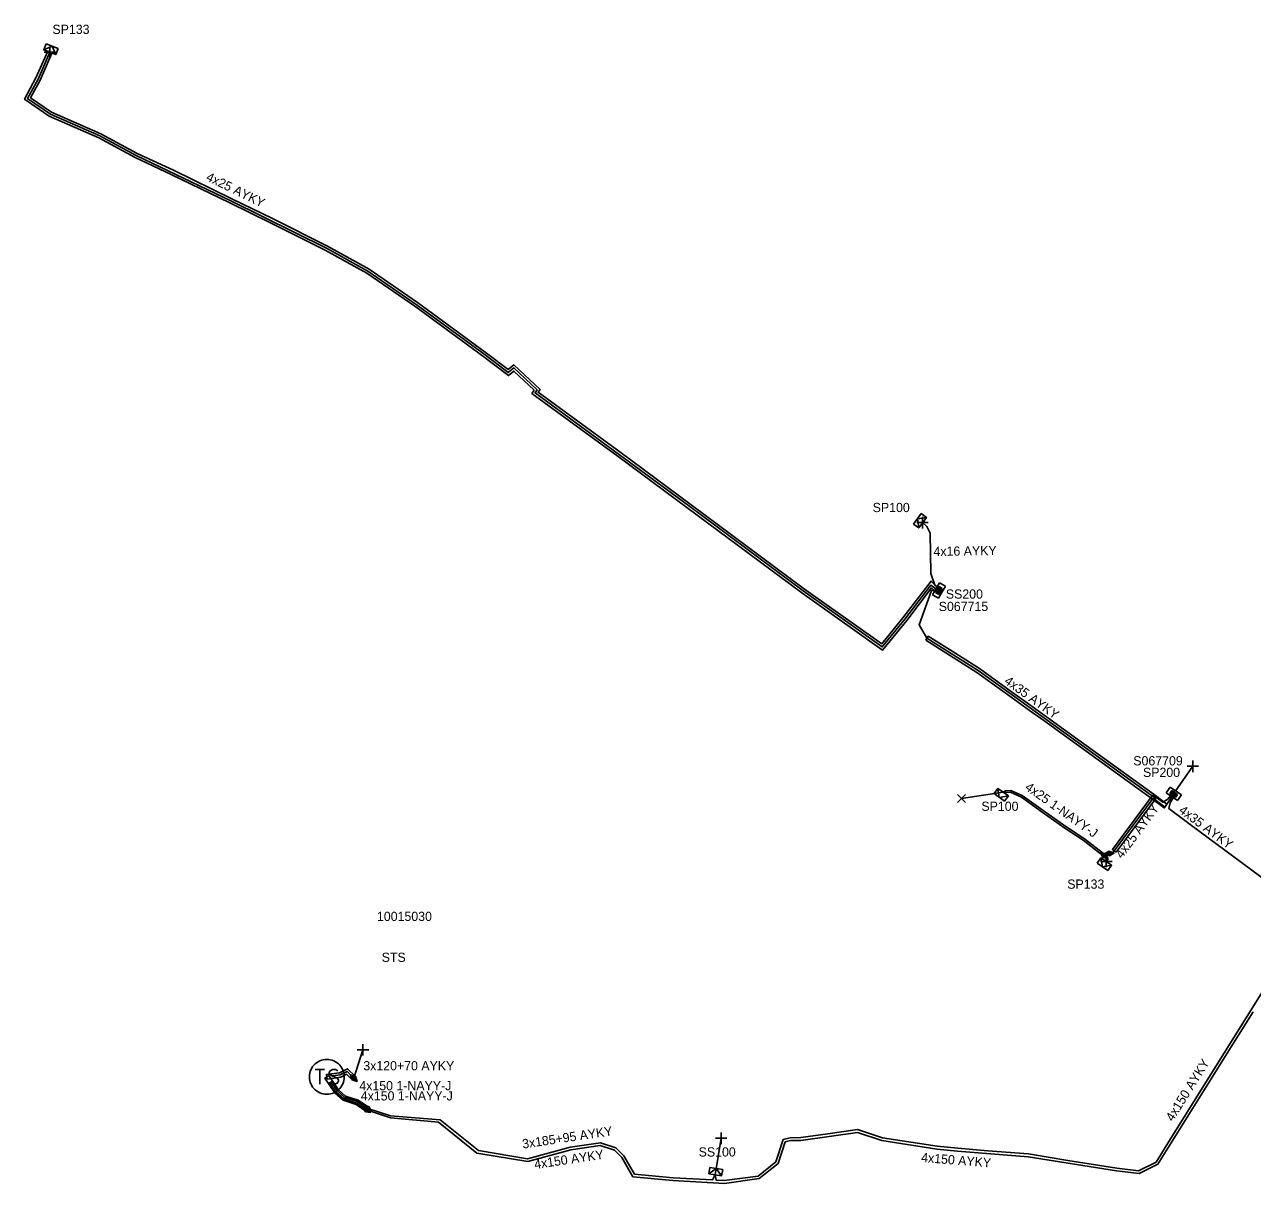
# Model space of a CAD drawing. Extents: x -748492 to -735633, y -1146251 to -1139940.
# Drawn here: x -737058.1 to -736925.2, y -1144906.3 to -1144780.8 of the extents above; entities that cross this region are included whole.
import ezdxf

# ---------------------------------------------------------------- set-up
doc = ezdxf.new("R2010")
doc.units = 0
for name, color, linetype in [('Vrstva 1', 7, 'Continuous'), ('Vrstva 19', 7, 'Continuous'), ('Vrstva 20', 7, 'Continuous'), ('Vrstva 25', 7, 'Continuous'), ('Vrstva 26', 7, 'Continuous'), ('Vrstva 27', 7, 'Continuous'), ('Vrstva 28', 7, 'Continuous'), ('Vrstva 29', 7, 'Continuous'), ('Vrstva 30', 7, 'Continuous'), ('Vrstva 31', 7, 'Continuous'), ('Vrstva 33', 7, 'Continuous'), ('Vrstva 34', 7, 'Continuous'), ('Vrstva 4', 7, 'Continuous'), ('Vrstva 5', 7, 'Continuous'), ('Vrstva 52', 7, 'Continuous'), ('Vrstva 54', 7, 'Continuous'), ('Vrstva 59', 7, 'Continuous'), ('Vrstva 6', 7, 'Continuous'), ('Vrstva 8', 7, 'Continuous'), ('Vrstva 9', 7, 'Continuous')]:
    doc.layers.add(name, color=color, linetype=linetype)

# ---------------------------------------------------------------- blocks, each defined once
blk = doc.blocks.new('NN870')
at = {"layer": 'Vrstva 4'}
for points in [[(0, -0.25), (0.5, 0), (0, 0.25), (-0.5, 0), (0, -0.25)], [(0.37, 0), (0, 0.19), (-0.36, 0), (0, -0.19), (0.37, 0)], [(0.24, 0), (0, 0.12), (-0.25, 0), (0, -0.12), (0.24, 0)], [(0.12, 0), (0, 0.06), (-0.13, 0), (0, -0.06), (0.12, 0)]]:
    blk.add_lwpolyline(points, dxfattribs=at)
blk = doc.blocks.new('NN800')
at = {"layer": 'Vrstva 1'}
for points in [[(-0.44, 0.44), (0.44, -0.44)], [(-0.44, -0.44), (0.44, 0.44)]]:
    blk.add_lwpolyline(points, dxfattribs=at)
blk = doc.blocks.new('NN620')
at = {"layer": 'Vrstva 8'}
for points in [[(0.75, 0), (-0.75, 0)], [(-0.75, 0), (-0.75, -0.75)], [(0.75, -0.75), (0.75, 0)], [(-0.75, -0.75), (0.75, -0.75)], [(0.37, -0.18), (-0.38, -0.18)], [(-0.38, -0.18), (-0.38, -0.56)], [(-0.38, -0.56), (0.37, -0.56)], [(0.32, -0.23), (-0.33, -0.23)], [(-0.33, -0.23), (-0.33, -0.51)], [(-0.33, -0.51), (0.32, -0.51)], [(0.27, -0.27), (-0.28, -0.27)], [(-0.28, -0.27), (-0.28, -0.46)], [(-0.28, -0.46), (0.27, -0.46)], [(0.23, -0.32), (-0.23, -0.32)], [(-0.23, -0.32), (-0.23, -0.42)], [(-0.23, -0.42), (0.23, -0.42)], [(-0.19, -0.37), (0.19, -0.37)], [(0.23, -0.42), (0.23, -0.32)], [(0.27, -0.46), (0.27, -0.27)], [(0.32, -0.51), (0.32, -0.23)], [(0.37, -0.56), (0.37, -0.18)]]:
    blk.add_lwpolyline(points, dxfattribs=at)
blk = doc.blocks.new('NN630')
at = {"layer": 'Vrstva 9'}
for points in [[(0, -0.7), (-0.7, 0)], [(-0.7, -0.7), (-0.7, 0), (0.7, 0), (0.7, -0.7)], [(-0.7, -0.7), (0.7, -0.7)], [(0, -0.7), (0.7, 0)]]:
    blk.add_lwpolyline(points, dxfattribs=at)
blk = doc.blocks.new('NN610')
at = {"layer": 'Vrstva 6'}
for points in [[(1.88, 0), (1.87, 0.2), (1.84, 0.39), (1.79, 0.58), (1.72, 0.77), (1.63, 0.94), (1.52, 1.11), (1.4, 1.26), (1.26, 1.4), (1.1, 1.53), (0.94, 1.63), (0.76, 1.72), (0.58, 1.8), (0.19, 1.88), (0.19, 1.88), (-0.01, 1.89), (-0.21, 1.88), (-0.4, 1.85), (-0.59, 1.8), (-0.78, 1.72), (-0.95, 1.63), (-1.12, 1.53), (-1.27, 1.4), (-1.41, 1.26), (-1.54, 1.11), (-1.64, 0.94), (-1.73, 0.77), (-1.8, 0.58), (-1.86, 0.39), (-1.89, 0.2), (-1.9, 0), (-1.89, -0.2), (-1.86, -0.39), (-1.8, -0.58), (-1.73, -0.77), (-1.64, -0.95), (-1.54, -1.11), (-1.41, -1.27), (-1.27, -1.41), (-1.12, -1.53), (-0.95, -1.64), (-0.78, -1.73), (-0.59, -1.8), (-0.4, -1.85), (-0.21, -1.88), (-0.01, -1.89), (0.19, -1.88), (0.39, -1.85), (0.58, -1.8), (0.76, -1.73), (0.94, -1.64), (1.1, -1.53), (1.26, -1.41), (1.4, -1.27), (1.52, -1.11), (1.63, -0.95), (1.72, -0.77), (1.79, -0.58), (1.84, -0.39), (1.87, -0.2), (1.88, 0)], [(-1.27, 0.78), (-0.26, 0.78)], [(-0.76, 0.78), (-0.76, -0.79)], [(1.19, 0.66), (0.94, 0.78), (0.62, 0.78), (0.37, 0.66), (0.24, 0.47), (0.24, 0.4), (0.37, 0.22), (1.12, -0.16), (1.25, -0.32), (1.25, -0.48), (1.12, -0.67), (0.87, -0.79), (0.62, -0.79), (0.49, -0.73), (0.24, -0.6)]]:
    blk.add_lwpolyline(points, dxfattribs=at)

msp = doc.modelspace()

# ---------------------------------------------------------------- linework, layer by layer
at = {"layer": 'Vrstva 20'}
for points in [[(-736959.58, -1144842.09), (-736959.88, -1144841.81), (-736962.58, -1144845.36), (-736965.18, -1144848.54), (-736973.94, -1144842.35), (-736986.36, -1144833.11), (-736993.8, -1144827.6), (-737003.15, -1144820.76), (-737002.92, -1144820.42), (-737005.12, -1144818.34), (-737005.69, -1144818.83), (-737008.49, -1144816.69), (-737015.82, -1144811.32), (-737021.03, -1144807.75), (-737025.51, -1144805.27), (-737031.45, -1144802.28), (-737035.85, -1144800.14), (-737042.18, -1144797.06), (-737046.11, -1144795.22), (-737050.02, -1144793.09), (-737055.39, -1144790.75), (-737058.07, -1144788.91), (-737056.83, -1144786.62), (-737055.56, -1144783.73), (-737055.1, -1144783.93), (-737056.38, -1144786.84), (-737057.41, -1144788.75), (-737055.15, -1144790.31), (-737049.8, -1144792.65), (-737045.89, -1144794.78), (-737041.96, -1144796.6), (-737035.63, -1144799.69), (-737031.23, -1144801.84), (-737025.27, -1144804.83), (-737020.77, -1144807.33), (-737015.53, -1144810.92), (-737008.19, -1144816.29), (-737005.71, -1144818.19), (-737005.1, -1144817.68), (-737002.26, -1144820.34), (-737002.47, -1144820.64), (-736993.5, -1144827.2), (-736986.06, -1144832.71), (-736973.64, -1144841.95), (-736965.28, -1144847.86), (-736962.98, -1144845.05), (-736959.94, -1144841.07), (-736959.24, -1144841.73)], [(-736960.52, -1144847.47), (-736960.26, -1144847.05), (-736957.67, -1144848.67), (-736954.7, -1144850.54), (-736951.36, -1144852.94), (-736949, -1144854.66), (-736947.45, -1144855.76), (-736945.62, -1144857.1), (-736935.66, -1144864.27), (-736934.4, -1144865.24), (-736934.7, -1144865.64), (-736935.96, -1144864.67), (-736945.91, -1144857.51), (-736947.74, -1144856.17), (-736949.29, -1144855.07), (-736951.65, -1144853.34), (-736954.98, -1144850.96), (-736957.94, -1144849.09)], [(-736939.91, -1144870.42), (-736940.31, -1144870.12), (-736936.01, -1144864.32), (-736935.61, -1144864.62)], [(-737025.13, -1144894.6), (-737024.11, -1144896.13), (-737023.31, -1144896.83), (-737021.96, -1144897.28), (-737020.84, -1144898.04), (-737021.12, -1144898.46), (-737022.18, -1144897.74), (-737023.57, -1144897.27), (-737024.49, -1144896.47), (-737025.55, -1144894.88)], [(-737025.38, -1144894.49), (-737023.98, -1144894.29), (-737023.1, -1144893.86), (-737022.24, -1144894.71), (-737022.6, -1144895.07), (-737023.2, -1144894.46), (-737023.82, -1144894.77), (-737025.3, -1144894.99)]]:
    msp.add_lwpolyline(points, close=True, dxfattribs=at)
at = {"layer": 'Vrstva 5'}
for points in [[(-736959.51, -1144842.09), (-736959.91, -1144842.09), (-736961.24, -1144845.8), (-736960.39, -1144847.26), (-736954.84, -1144850.75), (-736951.52, -1144853.15), (-736947.36, -1144856.14), (-736936.11, -1144864.25), (-736935.72, -1144864.35), (-736934.86, -1144865.01), (-736934.32, -1144864.69), (-736934.01, -1144864.31)], [(-736940.65, -1144870.56), (-736941.26, -1144870.58), (-736943.34, -1144868.98), (-736945.34, -1144867.65), (-736947.79, -1144865.92), (-736950.06, -1144864.3), (-736951.3, -1144863.74), (-736951.87, -1144863.8), (-736952.14, -1144863.93), (-736951.73, -1144863.98), (-736951.34, -1144863.94), (-736950.16, -1144864.48), (-736947.91, -1144866.08), (-736945.46, -1144867.81), (-736943.46, -1144869.14), (-736941.48, -1144870.66), (-736941.19, -1144870.79)], [(-736933.88, -1144864.42), (-736934.64, -1144865.56), (-736935.9, -1144864.59), (-736940.21, -1144870.42), (-736940.65, -1144870.56)], [(-736933.7, -1144864.52), (-736934.04, -1144865.07), (-736934.19, -1144865.71), (-736931.73, -1144867.53), (-736921.6, -1144875.04), (-736919.22, -1144874.32), (-736920.26, -1144873.68)], [(-736983.3, -1144905.34), (-736983.2, -1144905.93), (-736982.33, -1144905.98), (-736978.66, -1144905.48), (-736976.75, -1144903.94), (-736975.96, -1144901.54), (-736975.18, -1144901.33), (-736974.04, -1144901.32), (-736971.1, -1144900.91), (-736967.89, -1144900.45), (-736965.19, -1144901.34), (-736959.29, -1144902.26), (-736957.04, -1144902.48), (-736953.8, -1144902.74), (-736949.38, -1144903.09), (-736945.14, -1144903.78), (-736939.83, -1144904.63), (-736937.49, -1144904.9), (-736935.59, -1144903.96), (-736934.03, -1144901.45), (-736931.98, -1144898.17), (-736923.56, -1144884.72)], [(-737021.04, -1144898.33), (-737018.47, -1144899.18), (-737013.27, -1144899.65), (-737009.1, -1144902.99), (-737003.6, -1144903.9), (-736998.95, -1144902.66), (-736995.75, -1144902.18), (-736994.21, -1144902.67), (-736993.43, -1144903.48), (-736992.21, -1144905.55), (-736987.88, -1144905.98), (-736982.31, -1144906.28), (-736978.54, -1144905.76), (-736976.49, -1144904.12), (-736975.72, -1144901.78), (-736975.14, -1144901.63), (-736974.02, -1144901.62), (-736967.91, -1144900.75), (-736965.26, -1144901.64), (-736959.33, -1144902.56), (-736957.06, -1144902.78), (-736949.42, -1144903.39), (-736939.87, -1144904.93), (-736937.43, -1144905.2), (-736935.38, -1144904.19), (-736927.44, -1144891.48), (-736925.09, -1144887.72)], [(-737024.69, -1144894.65), (-737023.9, -1144894.53), (-737023.15, -1144894.16), (-737022.42, -1144894.89)], [(-737025.06, -1144895.34), (-737024.38, -1144896.37), (-737023.49, -1144897.14), (-737022.11, -1144897.6), (-737021.04, -1144898.33)], [(-737024.9, -1144895.22), (-737024.22, -1144896.23), (-737023.39, -1144896.96), (-737022.03, -1144897.42), (-737020.92, -1144898.17)], [(-737020.92, -1144898.17), (-737018.44, -1144898.95), (-737013.08, -1144899.4), (-737008.94, -1144902.71), (-737003.62, -1144903.6), (-736999.01, -1144902.36), (-736995.73, -1144901.88), (-736994.05, -1144902.41), (-736993.19, -1144903.3), (-736992.03, -1144905.27), (-736987.86, -1144905.68), (-736983.59, -1144905.9), (-736983.3, -1144905.34)]]:
    msp.add_lwpolyline(points, dxfattribs=at)
at = {"layer": 'Vrstva 52'}
for points in [[(-736959.41, -1144841.91), (-736959.97, -1144841.52), (-736962.78, -1144845.21), (-736965.23, -1144848.2), (-736973.79, -1144842.15), (-736986.21, -1144832.91), (-736993.65, -1144827.4), (-737002.81, -1144820.7), (-737002.59, -1144820.38), (-737005.11, -1144818.01), (-737005.7, -1144818.51), (-737008.34, -1144816.49), (-737015.67, -1144811.12), (-737020.9, -1144807.54), (-737025.39, -1144805.05), (-737035.74, -1144799.91), (-737046, -1144795), (-737049.91, -1144792.87), (-737055.27, -1144790.53), (-737057.74, -1144788.83), (-737056.6, -1144786.73), (-737055.33, -1144783.83)], [(-736959.29, -1144841.77), (-736959.54, -1144841.53), (-736959.95, -1144840.27), (-736960.02, -1144835.88), (-736960.38, -1144835.18), (-736960.86, -1144834.75)], [(-736941.19, -1144870.79), (-736940.77, -1144871.17), (-736940.97, -1144871.44)]]:
    msp.add_lwpolyline(points, dxfattribs=at)
at = {"layer": 'Vrstva 59'}
for points in [[(-736933.5, -1144863.87), (-736931.61, -1144861.13)], [(-736952.14, -1144863.93), (-736956.65, -1144864.62)], [(-737022.42, -1144894.89), (-737021.44, -1144891.81)], [(-736983.3, -1144905.34), (-736982.66, -1144901.39)]]:
    msp.add_lwpolyline(points, dxfattribs=at)

# ---------------------------------------------------------------- block references
at = {"layer": 'Vrstva 19'}
for p, rotation in [((-736941.19, -1144870.79), -37.77717136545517), ((-736940.65, -1144870.56), 3.47376526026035), ((-737022.42, -1144894.89), -45.282485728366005), ((-737020.95, -1144898.15), -34.923701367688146), ((-737021.04, -1144898.33), -32.93533191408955)]:
    msp.add_blockref('NN870', p, dxfattribs=dict(at, rotation=rotation))
at = {"layer": 'Vrstva 25'}
msp.add_blockref('NN610', (-737025.34, -1144894.74), dxfattribs=at)
at = {"layer": 'Vrstva 28'}
for p, rotation in [((-736959.41, -1144841.91), 60.12400841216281), ((-736933.88, -1144864.42), 145.43059169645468)]:
    msp.add_blockref('NN620', p, dxfattribs=dict(at, rotation=rotation))
at = {"layer": 'Vrstva 31'}
for p, rotation in [((-737055.33, -1144783.83), 159.20128886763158), ((-736960.86, -1144834.75), -126.19320829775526), ((-736952.14, -1144863.93), -35.90344366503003), ((-736940.97, -1144871.44), -34.53349169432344), ((-736983.3, -1144905.34), 170.8518527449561)]:
    msp.add_blockref('NN630', p, dxfattribs=dict(at, rotation=rotation))
at = {"layer": 'Vrstva 34'}
for p, rotation in [((-737055.33, -1144783.83), 45), ((-736960.86, -1144834.75), 45), ((-736931.61, -1144861.13), 45), ((-736940.97, -1144871.44), 45.00000009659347), ((-737021.44, -1144891.81), 45), ((-736982.66, -1144901.39), 45)]:
    msp.add_blockref('NN800', p, dxfattribs=dict(at, rotation=rotation))
msp.add_blockref('NN800', (-736956.65, -1144864.62), dxfattribs=at)

# ---------------------------------------------------------------- texts
at = {"layer": 'Vrstva 26'}
msp.add_text('10015030', height=1, dxfattribs=at).set_placement((-737019.92, -1144877.87))
at = {"layer": 'Vrstva 27'}
msp.add_text('STS', height=1, dxfattribs=at).set_placement((-737019.41, -1144882.3))
at = {"layer": 'Vrstva 29'}
for s, p in [('S067715', (-736959.11, -1144844.32)), ('S067709', (-736938.05, -1144861.03))]:
    msp.add_text(s, height=1, dxfattribs=at).set_placement(p)
at = {"layer": 'Vrstva 30'}
for s, p in [('SS200', (-736958.34, -1144842.98)), ('SP200', (-736937, -1144862.28))]:
    msp.add_text(s, height=1, dxfattribs=at).set_placement(p)
at = {"layer": 'Vrstva 33'}
for s, p in [('SP133', (-737055.05, -1144781.85)), ('SP100', (-736966.26, -1144833.61)), ('SP100', (-736954.49, -1144865.95)), ('SP133', (-736945.2, -1144874.38)), ('SS100', (-736985.1, -1144903.37))]:
    msp.add_text(s, height=1, dxfattribs=at).set_placement(p)
at = {"layer": 'Vrstva 54'}
for s, rotation, p in [('4x25 AYKY', 333.964, (-737038.51, -1144797.66)), ('4x16 AYKY', 0.914, (-736959.67, -1144838.37))]:
    msp.add_text(s, height=1, rotation=rotation, dxfattribs=at).set_placement(p)
at = {"layer": 'Vrstva 6'}
for s, rotation, p in [('4x35 AYKY', 324.293, (-736952.1, -1144852.09)), ('4x25 1-NAYY-J', 324.762, (-736949.86, -1144863.59)), ('4x25 AYKY', 53.508, (-736939.27, -1144871.19)), ('4x35 AYKY', 323.448, (-736933.21, -1144866.07)), ('4x150 AYKY', 57.96, (-736933.77, -1144899.64)), ('3x185+95 AYKY', 8.422, (-737004.12, -1144902.51)), ('4x150 AYKY', 8.43, (-737002.82, -1144904.72)), ('4x150 AYKY', 355.438, (-736961.04, -1144903.95))]:
    msp.add_text(s, height=1, rotation=rotation, dxfattribs=at).set_placement(p)
for s, p in [('3x120+70 AYKY', (-737021.4, -1144894.04)), ('4x150 1-NAYY-J', (-737021.83, -1144896.2)), ('4x150 1-NAYY-J', (-737021.67, -1144897.3))]:
    msp.add_text(s, height=1, dxfattribs=at).set_placement(p)

doc.saveas('drawing.dxf')
